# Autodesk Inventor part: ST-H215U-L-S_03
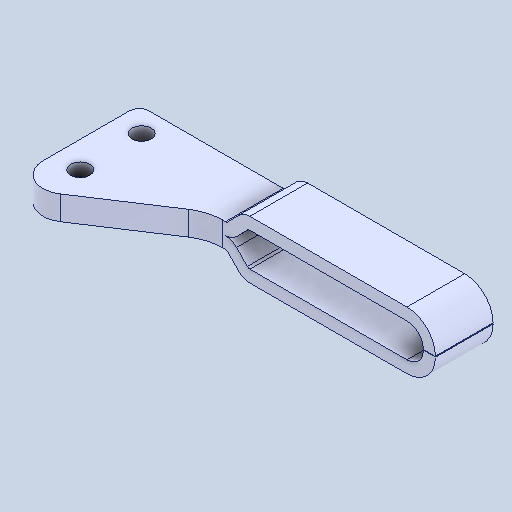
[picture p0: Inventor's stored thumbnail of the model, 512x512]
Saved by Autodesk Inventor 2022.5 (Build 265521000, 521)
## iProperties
Created: 2024-07
Part Number: ST-H215U-L-S_03
Material: 一般
Document SubType Name: Modeling
Designer: ImaoCorp
Density: 1 g/cm^3
Appearance: 既定
Author: ImaoCorp
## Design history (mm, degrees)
feature "ST-H215U-L-S_03"
node "ソリッド1"
